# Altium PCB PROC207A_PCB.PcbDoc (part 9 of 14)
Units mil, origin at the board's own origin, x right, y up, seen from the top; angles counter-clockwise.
Board outline 4094.49 x 3724.79 mil, 8 copper layers (Top Layer, L2_GND1, L3_SIG1, L4_PWR1, L5_PWR2, L6_SIG2, L7_GND2, Bottom Layer), stack 58.1 mil thick; 584 components, 399 nets, 8440 pads, 5258 vias.
Unrouted connection lines stored in the file: 9.
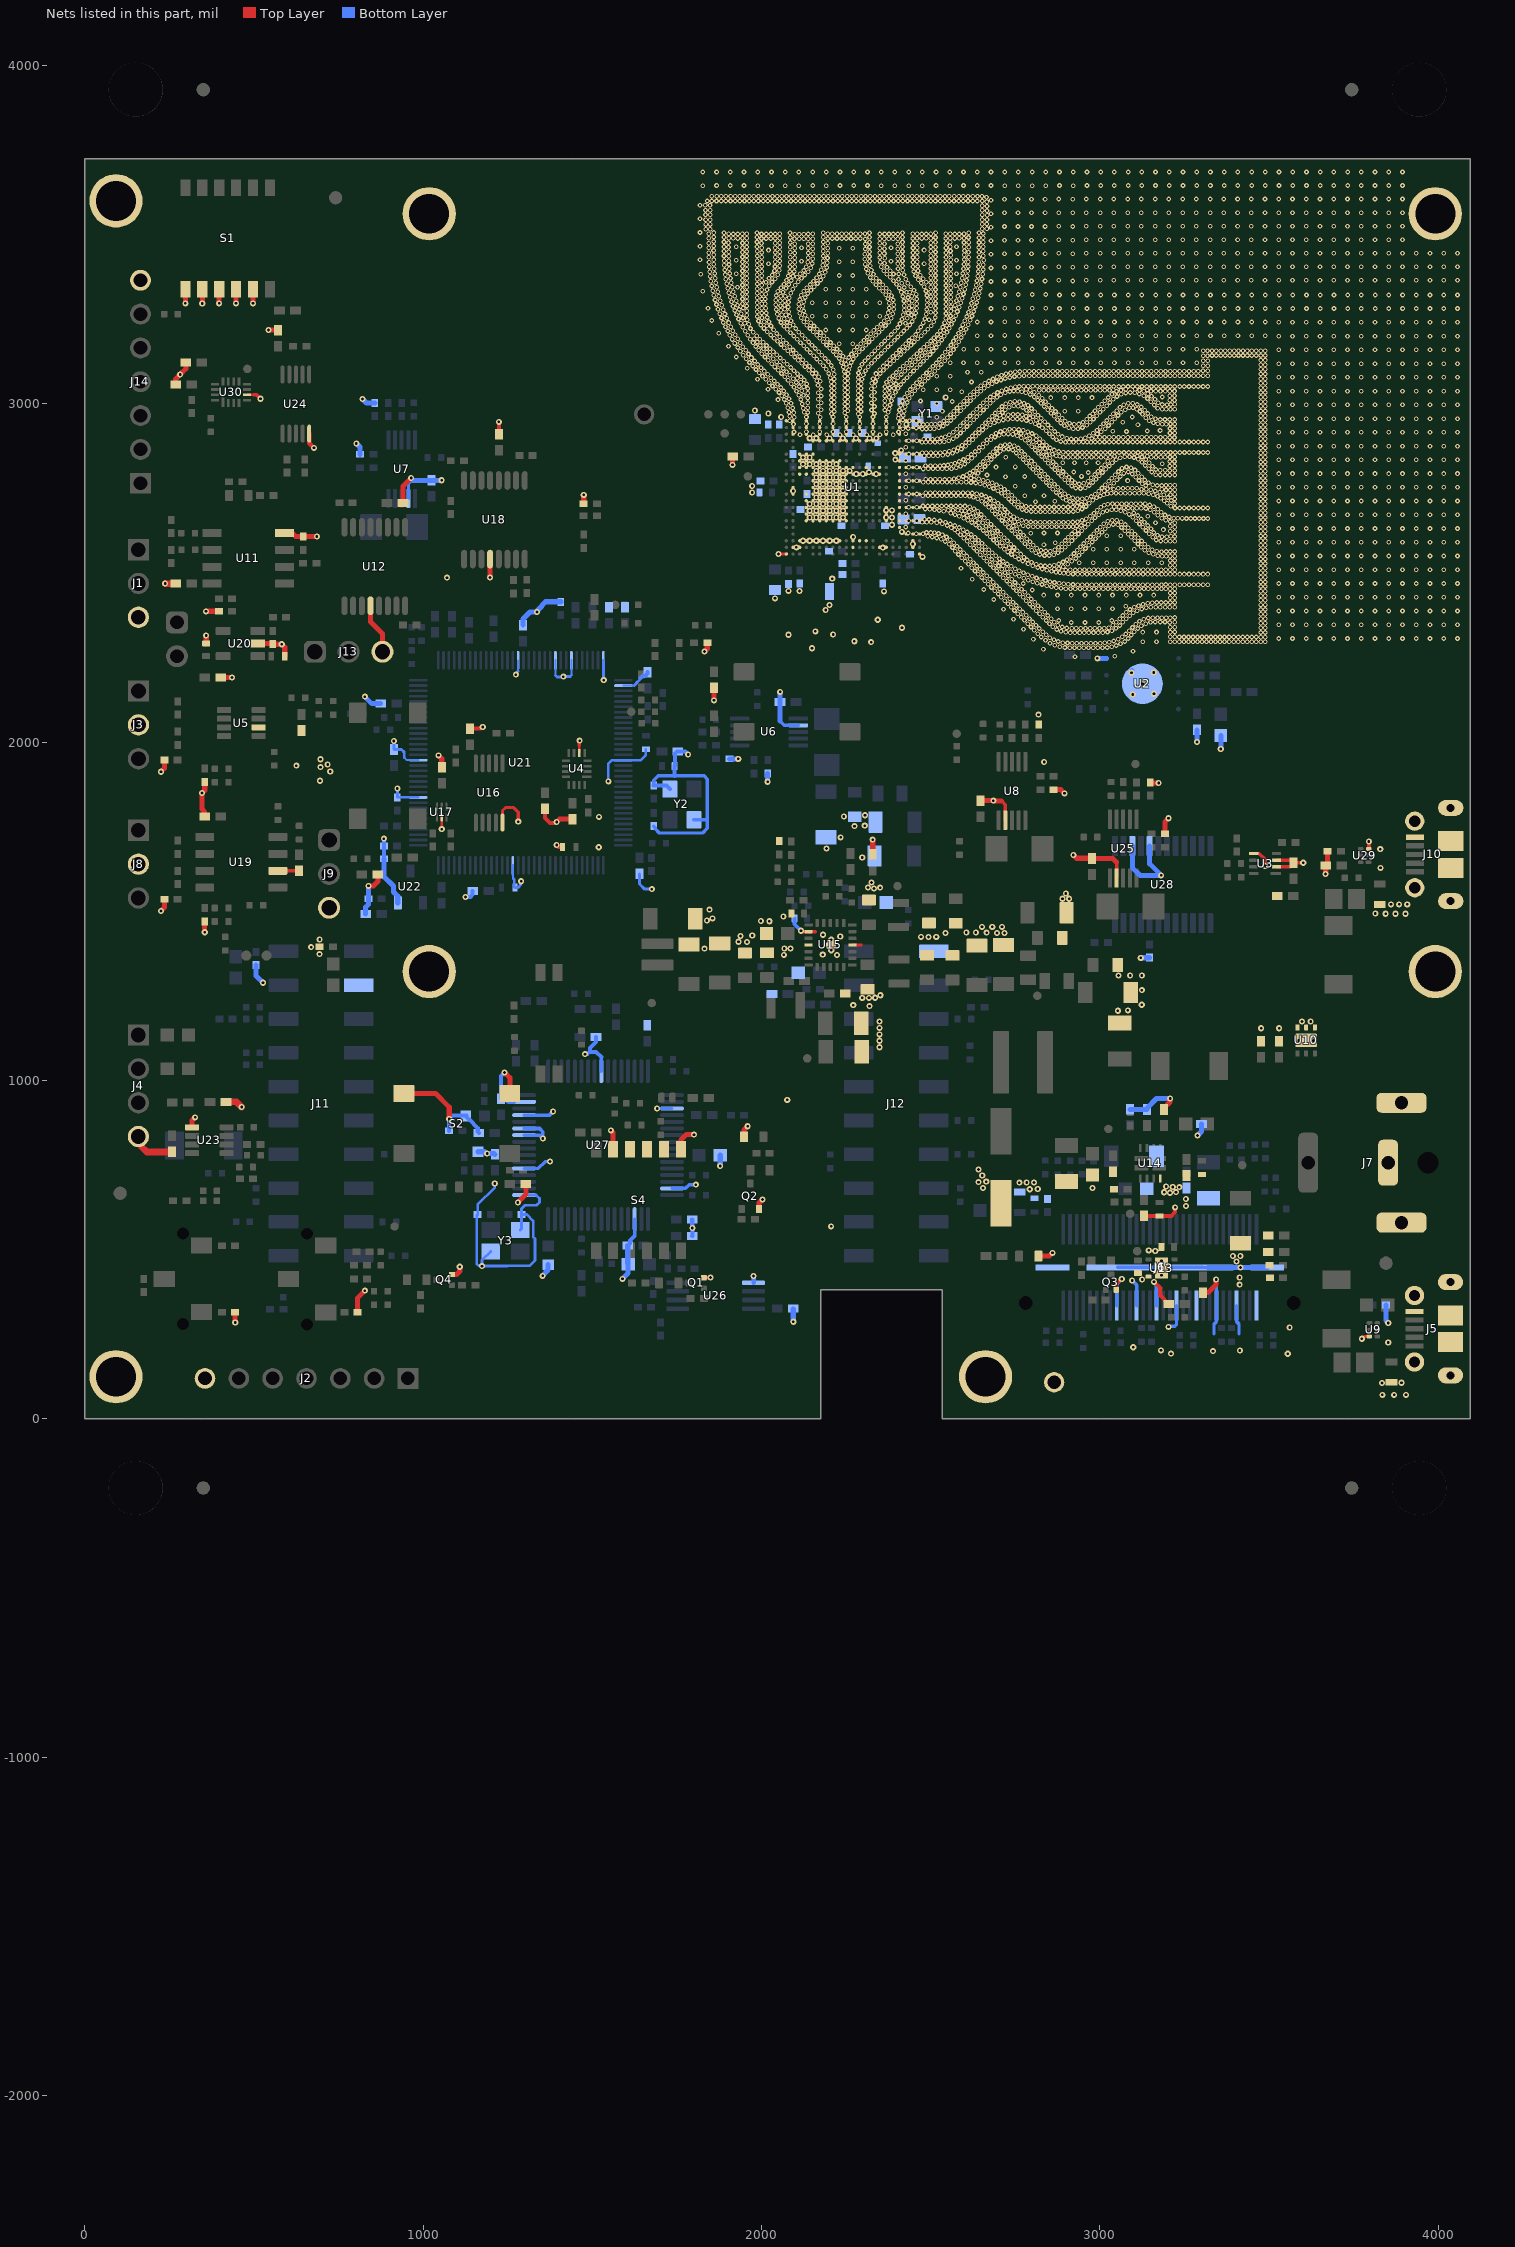
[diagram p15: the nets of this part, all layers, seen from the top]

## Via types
v1: diameter 13.77, hole 7, Top Layer to L2_GND1, tented top, 4306 vias
v2: diameter 18, hole 8, Top Layer to Bottom Layer, tented both sides, 946 vias
v3: diameter 19.68, hole 8, Top Layer to Bottom Layer, tented both sides, 6 vias

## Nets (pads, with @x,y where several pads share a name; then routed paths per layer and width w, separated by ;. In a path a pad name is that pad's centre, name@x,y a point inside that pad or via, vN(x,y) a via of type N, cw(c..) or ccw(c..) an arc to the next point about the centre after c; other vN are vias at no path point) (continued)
GND: (continued)
  other v1: 2926.59,2253.1 3044.2,2254.51 3098.09,2268.57 2833.35,2275.23 2911.35,2279.17 2925.22,2279.07 2938.99,2279.07 2952.76,2279.07 2966.53,2279.07 2980.3,2279.07 2994.39,2279.08 2896.92,2279.99 3008.14,2279.7 3021.9,2280.32 3035.58,2281.89 2881.78,2282.57 3048.76,2285.88 2866.94,2286.95 3061.39,2291.36 2852.8,2293.13 2918.34,2293.11 2932.11,2293.11 2945.88,2293.11 2959.65,2293.11 2973.42,2293.11 2987.19,2293.11 3000.96,2293.11 2904.57,2293.32 3014.71,2293.73 2890.86,2294.67 3028.39,2295.3 3126.81,2297.3 3167.44,2297.3 3208.06,2297.3 3221.57,2297.3 3235.41,2297.3 3248.75,2297.3 3262.09,2297.3 3275.43,2297.3 3288.77,2297.3 3302.1,2297.3 3315.44,2297.3 3328.78,2297.3 3342.12,2297.3 3355.46,2297.3 3368.8,2297.3 3382.14,2297.3 3395.47,2297.3 3408.81,2297.3 3422.15,2297.3 3435.49,2297.3 3448.83,2297.3 3462.17,2297.3 3475.51,2297.3 3488.84,2297.3 2877.51,2298.05 3073.43,2298.05 3041.57,2299.29 2839.39,2301.43 2864.55,2302.69 2803.81,2304.74 3054.2,2304.77 3084.07,2306.79 3529.15,2306.79 3569.78,2306.79 3610.4,2306.79 3651.03,2306.79 3691.65,2306.79 3732.28,2306.79 3772.9,2306.79 3813.53,2306.79 3854.15,2306.79 3894.78,2306.79 3935.4,2306.79 3976.03,2306.79 4016.65,2306.79 4057.28,2306.79 2852.41,2309.18 2827.35,2310.99 3235.41,2311.07 3248.75,2311.07 3262.09,2311.07 3275.43,2311.07 3288.77,2311.07 3302.1,2311.07 3315.44,2311.07 3328.78,2311.07 3342.12,2311.07 3355.46,2311.07 3368.8,2311.07 3382.14,2311.07 3395.47,2311.07 3408.81,2311.07 3422.15,2311.07 3435.49,2311.07 3448.83,2311.07 3462.17,2311.07 3475.51,2310.88 3488.84,2310.88 3066.24,2311.46 3208.06,2311.52 3221.57,2311.59 3092.61,2317.19 2841.33,2317.36 3076.88,2320.2 2816.52,2321.09 2912.67,2324.26 2926.44,2324.26 2940.21,2324.26 2953.98,2324.26 2967.75,2324.26 2981.52,2324.26 2995.29,2324.26 3009.06,2324.28 2898.92,2324.98 3475.51,2324.47 3488.84,2324.47 3022.73,2325.93 3126.81,2325.74 3167.44,2325.74 3208.06,2325.74 3221.57,2325.88 2830.99,2326.45 3102.3,2326.99 2885.48,2327.98 3035.86,2330.06 3086.9,2329.65 2806.46,2331.13 2774.27,2334.26 2872.81,2333.37 2821.25,2336.19 3112.11,2336.23 2916.61,2337.2 2930.38,2337.2 2944.15,2337.2 2957.92,2337.2 2971.69,2337.2 2985.46,2337.2 2999.23,2337.2 3013,2337.22 3048.01,2336.56 2902.73,2337.86 3475.51,2338.06 3488.84,2338.06 3026.67,2338.87 3096.63,2339.39 3208.06,2339.96 3221.57,2340.17 2796.72,2340.87 2861.33,2340.98 2889.19,2340.86 3058.66,2345.29 3123.08,2344.54 2811.52,2345.93 2876.13,2346.04 3038.34,2346.18 3529.15,2347.41 3569.78,2347.41 3610.4,2347.41 3651.03,2347.41 3691.65,2347.41 3732.28,2347.41 3772.9,2347.41 3813.53,2347.41 3854.15,2347.41 3894.78,2347.41 3935.4,2347.41 3976.03,2347.41 4016.65,2347.41 4057.28,2347.41 3106.47,2349.02 2851.19,2350.3 2786.98,2350.6 3135.4,2350.7 3475.51,2351.65 3488.84,2351.65 2915.77,2353.86 2956.4,2353.86 2997.02,2353.86 3207.21,2354.18 2865.03,2354.36 3048.99,2354.82 3068.31,2355.11 3149.76,2354.49 3221.57,2354.46 2801.78,2355.66 3164.12,2355.6 3178.49,2355.6 3192.85,2355.6 3117.44,2357.34 2841.45,2360.03 2878.75,2360.11 3035.64,2359.93 2777.25,2360.34 2744.74,2363.78 3129.76,2363.5 2856.25,2365.09 3058.6,2364.82 3078.05,2364.84 3475.51,2365.24 3488.84,2365.24 2792.04,2365.4 3143,2367.29 3156.72,2368.4 3170.49,2368.4 3183.23,2368.4 3195.96,2368.4 3208.06,2368.4 3221.57,2368.76 2767.51,2370.08 2831.72,2369.77 3088.24,2374.1 2782.3,2375.14 2846.51,2374.83 3068.27,2374.63 3475.51,2378.83 3488.84,2378.83 2757.77,2379.81 2821.98,2379.51 3099.06,2382.62 3078.52,2384.04 2772.57,2384.87 2836.78,2384.57 3529.15,2388.04 3569.78,2388.04 3610.4,2388.04 3651.03,2388.04 3691.65,2388.04 3732.28,2388.04 3772.9,2388.04 3813.53,2388.04 3854.15,2388.04 3894.78,2388.04 3935.4,2388.04 3976.03,2388.04 4016.65,2388.04 4057.28,2388.04 2812.24,2389.24 3111.21,2389.11 2748.03,2389.55 2715.53,2392.99 3089.3,2392.41 3475.51,2392.41 3488.84,2392.41 2827.04,2394.3 3124.03,2394.11 2762.83,2394.61 2875.15,2394.49 2915.77,2394.49 2956.4,2394.49 2997.02,2394.49 3037.65,2394.49 3137.29,2397.83 2738.3,2399.29 2802.51,2398.98 3101.45,2398.99 3151,2399.18 3165.07,2399.55 3179.14,2399.55 3193.2,2399.55 3207.27,2399.55 3221.34,2399.55 3076.93,2401.8 2817.3,2404.04 3114.42,2403.73 2753.09,2404.35 3475.51,2406 3488.84,2406 3127.69,2407.85 2728.56,2409.02 2792.77,2408.72 3141.58,2410.98 3155.34,2412.2 3168.53,2413.17 2743.36,2414.08 2807.57,2413.78 3181.72,2413.35 3194.92,2413.35 3208.11,2413.35 3221.3,2413.35 2718.82,2418.76 2783.03,2418.45 3475.51,2419.59 3488.84,2419.59 2686.31,2422.2 2733.62,2423.82 2797.83,2423.51 3208.44,2427.18 3221.32,2427.22 2773.3,2428.19 2709.09,2428.5 3529.15,2428.66 3569.78,2428.66 3610.4,2428.66 3651.03,2428.66 3691.65,2428.66 3732.28,2428.66 3772.9,2428.66 3813.53,2428.66 3854.15,2428.66 3894.78,2428.66 3935.4,2428.66 3976.03,2428.66 4016.65,2428.66 4057.28,2428.66 2788.09,2433.25 3475.51,2433.18 3488.84,2433.18 2723.88,2433.56 2834.52,2435.11 2875.15,2435.11 2915.77,2435.11 2956.4,2435.11 2997.02,2435.11 3037.65,2435.11 3078.27,2435.11 3118.9,2435.11 3159.52,2435.11 2699.35,2438.24 2763.56,2437.93 3208.45,2441.06 3221.33,2441.1 2714.15,2443.29 2778.36,2442.99 3475.51,2446.77 3488.84,2446.77 2689.61,2447.97 2753.82,2447.66 2800.03,2450.05 2656.9,2451.41 2704.41,2453.03 2768.62,2452.72 2899.5,2453.67 2913.45,2453.5 2927.55,2453.5 2941.58,2453.5 2955.35,2453.5 2969.12,2453.5 2982.89,2453.5 2996.66,2453.5 3010.43,2453.5 3024.2,2453.5 3037.97,2453.5 3051.74,2453.5 3065.51,2453.97 3078.5,2453.97 3091.49,2453.97 3104.49,2453.97 3117.48,2453.97 3130.47,2453.97 3143.47,2453.97 3156.46,2453.97 3169.45,2453.97 3182.45,2453.97 3195.44,2453.97 3208.43,2453.97 3221.43,2453.97 2885.13,2455.2 2870.95,2457.28 2679.88,2457.71 2744.09,2457.4 2857.09,2459.64 3475.51,2460.36 3488.84,2460.36 2694.67,2462.77 2758.88,2462.46 2842.97,2462.74 2829.23,2466.17 2934.69,2466.04 2948.46,2466.04 2962.23,2466.04 2976,2466.04 2989.77,2466.04 3003.54,2466.04 3017.31,2466.04 3031.08,2466.04 3044.85,2466.04 3058.62,2466.04 3072.39,2466.04 3086.16,2466.04 3099.93,2466.04 3113.7,2466.04 3127.47,2466.04 3141.24,2466.04 3155.01,2466.04 3168.78,2466.04 3182.55,2466.04 3208.18,2466.04 3222.06,2466.04 3235.94,2466.04 3249.82,2466.04 3263.71,2466.04 3277.57,2466.04 3291.44,2466.04 3305.3,2466.04 3319.16,2466.04 2734.35,2467.14 2907.18,2467.22 2920.93,2466.55 3194.87,2466.42 2670.14,2467.45 2893.44,2468.14 2773.99,2469.14 3529.15,2469.29 3569.78,2469.29 3610.4,2469.29 3651.03,2469.29 3691.65,2469.29 3732.28,2469.29 3772.9,2469.29 3813.53,2469.29 3854.15,2469.29 3894.78,2469.29 3935.4,2469.29 3976.03,2469.29 4016.65,2469.29 4057.28,2469.29 2815.55,2470.09 2879.82,2470.16 2749.15,2472.2 2866.2,2472.18 2684.94,2472.51 3475.51,2473.94 3488.84,2473.94 2801.85,2474.72 2852.67,2474.77 2660.4,2477.18 2724.61,2476.87 2839.32,2478.12 2788.68,2479.43 2623.14,2481.91 2675.2,2482.24 2739.41,2481.93 2825.96,2481.47 2775.36,2484.89 2812.85,2485.69 2650.67,2486.92 2714.88,2486.61 3475.51,2487.53 3488.84,2487.53 2762.25,2491 2799.89,2490.33 2665.46,2491.98 2729.67,2491.67 2786.92,2494.97 2640.93,2496.66 2705.14,2496.35 2749.7,2497.07 2934.74,2497.18 2948.51,2497.18 2962.28,2497.18 2976.05,2497.18 2989.82,2497.18 3003.59,2497.18 3017.36,2497.18 3031.13,2497.18 3044.9,2497.18 3058.67,2497.18 3072.44,2497.18 3086.21,2497.18 3099.98,2497.18 3113.75,2497.18 3127.52,2497.18 3141.29,2497.18 3155.06,2497.18 3168.83,2497.18 3182.6,2497.18 3195.05,2496.76 3208.18,2497.19 3222.06,2497.19 3235.94,2497.19 3249.82,2497.19 3263.71,2497.19 3277.57,2497.19 3291.44,2497.19 3305.3,2497.19 3319.16,2497.19 2907.22,2498.21 2920.98,2497.54 2893.51,2499.42 2774.43,2500.77 2882.23,2500.62 3475.51,2501.12 3488.84,2501.12 2655.73,2501.72 2719.93,2501.41 2870.63,2502.5 2737.02,2503.98 2857.15,2505.18 2695.4,2506.09 2631.19,2506.39 2761.99,2506.66 2843.62,2508.42 2899.1,2509.15 2926.94,2509.24 2940.87,2510.03 2954.79,2510.03 2968.71,2510.03 2982.63,2509.68 2995.9,2509.68 3009.17,2509.68 3022.44,2509.68 3035.71,2509.68 3048.98,2509.68 3062.25,2509.68 3075.52,2509.68 3088.79,2509.68 3102.06,2509.68 3115.32,2509.68 3128.59,2509.68 3141.86,2509.68 3155.13,2509.68 3168.4,2509.68 3181.67,2509.68 3194.94,2509.68 3208.21,2509.68 3221.48,2509.68 3529.15,2509.91 3569.78,2509.91 3610.4,2509.91 3651.03,2509.91 3691.65,2509.91 3732.28,2509.91 3772.9,2509.91 3813.53,2509.91 3854.15,2509.91 3894.78,2509.91 3935.4,2509.91 3976.03,2509.91 4016.65,2509.91 4057.28,2509.91 2710.2,2511.14 2913.02,2510.34 2645.99,2511.45 2830.32,2512.16 2865.55,2512.13 2726.35,2512.78 2749.64,2512.76 2879.18,2513.68 2589.56,2514.34 3475.51,2514.71 3488.84,2514.71 2621.46,2516.13 2685.66,2515.82 2816.46,2516.66 2892.24,2518.9 2737.83,2519.84 2636.25,2521.19 2700.46,2520.88 2838.25,2520.98 2852.02,2521.25 2714.21,2522.14 2801.95,2522.09 2825.7,2522.57 2865.67,2523 3208.61,2523.51 3221.49,2523.56 2611.72,2525.87 2675.93,2525.56 2811.67,2526.24 2905.32,2525.89 2726.02,2526.92 2878.85,2526.99 2787.97,2528.16 3475.51,2528.3 3488.84,2528.3 2626.51,2530.93 2690.72,2530.62 2939.68,2530.81 2980.31,2530.81 3020.93,2530.81 3061.56,2530.81 3102.18,2530.81 3142.81,2530.81 3183.43,2530.81 2703.48,2531.45 2797.94,2531.93 2891.36,2532.75 2666.19,2535.3 2714.52,2534.48 2601.98,2535.6 2772.15,2535.99 2917.27,2535.49 3208.63,2537.39 3221.5,2537.44 2785.99,2538.83 2903.18,2539.82 2616.78,2540.66 2680.99,2540.35 2760.79,2541.78 3475.51,2541.89 3488.84,2541.89 2703.46,2542.69 2928.62,2543.4 2656.45,2545.03 2592.24,2545.34 2775.86,2546.83 2749.65,2548.39 2913.82,2548.55 2671.25,2550.09 3184.99,2550.12 3196.46,2550.12 3207.99,2550.24 3221.49,2550.18 2607.04,2550.4 2692.4,2550.89 3529.15,2550.54 3569.78,2550.54 3610.4,2550.54 3651.03,2550.54 3691.65,2550.54 3732.28,2550.54 3772.9,2550.54 3813.53,2550.54 3854.15,2550.54 3894.78,2550.54 3935.4,2550.54 3976.03,2550.54 4016.65,2550.54 4057.28,2550.54 2836.41,2552.27 2850.18,2552.17 3171.36,2551.33 2938.45,2553.14 2582.51,2555.08 2646.72,2554.77 2739.18,2554.92 2822.92,2555.03 2863.7,2554.74 3157.98,2555.46 3475.51,2555.47 3488.84,2555.47 2765.88,2556.32 2923.65,2558.2 2597.3,2560.14 2661.51,2559.83 2681.9,2559.81 2876.48,2559.89 2810.22,2560.36 3144.91,2560.52 2727.84,2562.66 2948.18,2562.88 3182.3,2563.68 3196.14,2564.01 3208.62,2564.01 3221.5,2564.06 2572.77,2564.81 2636.98,2564.51 2853.55,2564.92 3168.6,2565.06 2741.86,2565.34 2756.14,2566.05 2839.9,2565.35 2798.79,2568.05 2826.29,2567.78 2888.01,2567.41 2933.39,2567.93 3133.09,2567.35 2671.7,2569.05 3475.51,2569.06 3488.84,2569.06 2587.57,2569.87 2651.78,2569.57 2866.41,2569.41 3155.5,2569.31 2717.11,2571.1 2980.31,2570.81 3020.93,2570.81 3061.56,2570.81 3102.18,2570.81 2813.59,2573.11 2957.92,2572.61 2627.24,2574.24 2732.85,2574.55 2564.43,2575.74 2746.41,2575.79 3143.63,2576.28 2878.03,2576.93 2898.14,2576.74 3122.72,2576.49 2661.5,2578.3 2788.76,2577.48 2943.12,2577.67 2642.04,2579.3 2577.83,2579.61 2706.23,2579.54 2721.87,2580.47 2803.56,2582.54 2967.66,2582.35 3475.51,2582.65 3488.84,2582.65 2617.51,2583.98 2834.84,2584.06 2554.63,2585.24 2736.67,2585.53 3112.99,2586.23 3133.23,2585.31 2779.03,2587.22 2887.77,2586.67 2907.88,2586.47 2651.76,2588.04 2952.86,2587.41 2632.3,2589.04 2696.02,2588.79 2568.09,2589.35 2712.14,2590.21 2868.76,2589.67 3529.15,2591.16 3569.78,2591.16 3610.4,2591.16 3651.03,2591.16 3691.65,2591.16 3732.28,2591.16 3772.9,2591.16 3813.53,2591.16 3854.15,2591.16 3894.78,2591.16 3935.4,2591.16 3976.03,2591.16 4016.65,2591.16 4057.28,2591.16 2793.82,2592.28 2977.39,2592.09 2543.61,2593.6 2607.77,2593.72 2726.93,2595.26 3123.49,2595.04 3180.56,2594.82 3194.5,2594.46 3208.36,2594.51 3221.5,2594.66 2917.62,2596.21 3103.25,2595.96 3475.51,2596.24 3488.84,2596.24 2641.5,2597.22 2769.29,2596.95 2897.51,2596.4 2962.6,2597.15 2685.82,2598.03 3167.16,2597.98 2558.07,2598.79 2622.57,2598.78 2531.29,2600.29 2702.4,2599.94 2784.08,2602.01 2987.13,2601.82 2517.98,2603.98 2598.03,2603.45 2717.19,2605 3113.75,2604.78 2611.07,2606.27 2630.9,2606.02 2907.24,2606.14 2927.35,2605.95 3093.51,2605.7 2504.88,2606.82 2546.99,2606.96 2759.55,2606.69 2972.34,2606.88 3156.22,2606.36 2676.11,2607.8 3183.92,2607.85 3197.47,2607.65 3221.39,2608.25 3209.35,2608.56 2491.38,2609.54 2692.66,2609.68 3475.51,2609.83 3488.84,2609.83 3020.93,2610.81 3061.56,2610.81 2774.35,2611.75 2996.87,2611.56 3170.64,2611.52 2588.3,2613.19 2534.8,2613.37 2619.67,2613.98 2599.28,2614.99 2707.46,2614.74 3104.02,2614.52 2917.38,2615.46 2937.09,2615.68 3083.78,2615.44 3146.49,2616.09 2457.68,2616.75 2477.37,2616.75 2523.19,2617.11 2665.84,2616.97 2749.81,2616.43 2982.07,2616.62 2795.57,2618.2 2434.18,2618.45 2835.01,2618.45 2875.01,2618.45 2487.76,2619.98 2500.28,2619.88 2511.21,2619.33 2682.93,2619.42 3159.79,2619.92 2579.89,2620.84 3006.61,2621.3 2608.23,2621.64 2764.61,2621.49 3221.41,2621.83 2925.56,2623.25 3094.28,2624.25 3208.53,2623.91 3475.51,2623.42 3488.84,2623.42 2697.72,2624.48 3074.16,2625.07 2655.58,2626.15 2740.08,2626.16 2946.83,2625.42 3136.75,2625.83 2991.81,2626.36 2570.93,2627.89 2596.18,2628.3 2673.19,2629.15 2935.91,2628.43 3188.1,2628.72 2754.87,2631.22 3016.34,2631.03 3151.55,2630.89 3529.15,2631.79 3569.78,2631.79 3610.4,2631.79 3651.03,2631.79 3691.65,2631.79 3732.28,2631.79 3772.9,2631.79 3813.53,2631.79 3854.15,2631.79 3894.78,2631.79 3935.4,2631.79 3976.03,2631.79 4016.65,2631.79 4057.28,2631.79 2561.4,2634.26 2687.98,2634.21 3084.54,2633.99 2584.1,2634.93 2644.5,2634.32 2956.56,2635.16 3064.13,2634.89 2426.46,2636.22 2730.34,2635.9 3001.55,2636.09 3127.01,2635.57 3221.42,2635.41 2803.06,2636.83 2816.98,2636.68 2830.75,2636.68 2844.52,2636.68 2858.29,2636.68 2872.06,2636.68 2885.83,2636.68 2908.92,2636.92 2920.86,2637.21 3475.51,2637 3488.84,2637 2788.63,2637.69 2897.59,2637.37 2663.45,2638.89 3208.09,2638.61 2743.91,2639.42 2931.48,2639.32 2548.71,2640.66 2571.46,2640.62 2773.49,2640.35 2945.05,2640.79 3026.34,2640.5 3141.81,2640.63 2633.27,2642.29 2678.25,2643.95 3039.71,2643.82 3053.47,2643.53 3074.75,2643.67 2760.67,2644.84 2966.3,2644.89 3117.28,2645.3 2534.13,2645.79 2558.38,2645.32 2720.6,2645.64 3011.55,2645.56 2955.26,2647.23 2517.87,2649.24 2642.16,2648.66 2653.71,2648.63 2733.95,2648.99 3164.67,2649.11 3221.43,2648.99 2543.84,2650.04 2621.61,2649.62 2474.84,2650.36 2488.6,2650.32 2502.16,2650.71 2796.33,2651.02 2810.1,2650.72 2823.87,2650.72 2837.64,2650.72 2851.41,2650.72 2865.18,2650.72 2878.95,2650.72 2892.72,2650.72 2906.49,2650.72 2920.25,2650.93 3132.07,2650.36 3475.51,2650.7 3488.84,2650.7 2748.82,2651.33 2933.96,2652.28 3063.39,2651.46 2782.62,2652.37 3023.22,2652.86 3208.4,2652.66 2527.43,2654.03 2668.51,2653.69 2435.21,2655.07 2459.01,2655.09 2976.18,2654.36 3107.54,2655.04 2710.87,2655.37 2769.31,2655.87 2947.25,2655.88 3036.59,2656.18 3050.35,2655.89 2510.64,2656.95 2609.47,2656.38 2631.64,2656.65 3195.05,2656.52 2495.13,2658.64 2481.7,2659.36 2645.43,2659.75 2723.75,2659.33 2737.4,2659.38 3122.33,2660.1 2756.36,2660.55 2960.03,2661 3230.91,2661.74 3243.52,2661.69 3256.12,2661.31 3268.73,2661.31 3281.34,2661.31 3293.95,2661.31 3306.55,2661.31 3319.16,2661.31 2597.52,2662.41 3182.67,2662.66 3218.3,2662.53 2658.77,2663.42 2985.86,2663.99 2620.31,2664.92 2701.13,2665.11 3097.8,2664.78 3475.51,2664.38 3488.84,2664.38 3205.11,2665.97 2745.7,2666.38 2584.67,2667.95 2971.88,2667.85 3141.55,2667.97 2608.53,2670.29 2635.64,2669.44 3112.09,2670.3 2716.94,2671.24 3171.77,2670.96 3192.92,2671.93 2571.97,2672.9 2649.04,2673.16 2735.64,2672.95 2996.45,2673.01 3529.15,2672.41 3569.78,2672.41 3610.4,2672.41 3651.03,2672.41 3691.65,2672.41 3732.28,2672.41 3772.9,2672.41 3813.53,2672.41 3854.15,2672.41 3894.78,2672.41 3935.4,2672.41 3976.03,2672.41 4016.65,2672.41 4057.28,2672.41 2596.05,2673.79 3087.16,2673.52 2691.39,2674.85 2426.46,2675.59 2558.96,2677.22 2982.77,2676.49 2624.54,2677.39 2705.05,2678.24 3100.42,2677.79 3475.51,2678.07 3488.84,2678.07 2727.24,2680.14 3008.33,2680 3075.16,2680.26 3161.23,2679.87 3181.98,2680.35 2614.09,2681.93 2797.13,2682.04 2810.9,2681.86 2824.67,2681.86 2838.44,2681.86 2852.21,2681.86 2865.98,2681.86 2879.75,2681.86 2893.52,2681.86 2907.29,2681.86 2921.06,2682.12 2538.47,2682.63 2639.2,2682.8 2783.49,2683.92 2525.16,2685.27 2591.08,2684.72 2602.44,2684.32 2681.66,2684.59 2934.64,2684.4 3021.27,2684.69 3062.18,2684.86 2551.86,2685.48 2565.94,2685.67 2579.73,2685.67 2992.6,2686.01 3034.83,2687.11 3048.6,2687.16 3149.62,2687.09 2511.56,2687.34 2719.6,2687.94 2770.39,2688.15 2497.79,2688.86 3171.71,2689.04 2483.87,2689.61 2697.76,2689.95 2947.47,2689.39 2627.97,2690.76 3136.38,2691.12 3096.58,2692.1 3109.21,2691.89 3122.72,2691.43 3475.51,2691.76 3488.84,2691.76 3071.48,2693.18 3083.86,2692.6 3222.16,2692.58 3235.94,2692.46 3249.82,2692.46 3263.71,2692.46 3277.57,2692.46 3291.44,2692.46 3305.3,2692.46 3319.16,2692.46 2435.21,2694.44 2459.01,2694.46 2671.92,2694.32 2758.24,2694.64 3003.19,2694.62 2615.23,2695.99 2795.72,2695.51 2809.49,2695.51 2823.26,2695.51 2837.03,2695.51 2850.8,2695.51 2864.57,2695.51 2878.34,2695.51 2892.11,2695.51 2905.88,2695.51 2919.65,2695.51 3042.23,2695.72 3057.9,2695.86 2685.69,2697.02 2709.4,2697.2 2959.04,2696.86 3160.01,2696.3 2491.48,2698.3 2505.25,2698.3 2519.02,2698.3 2532.79,2698.3 2546.56,2698.3 2560.33,2698.3 2574.1,2698.3 2587.87,2698.3 2601.64,2698.21 2781.94,2697.88 2932.81,2698.04 3209.41,2697.59 2477.5,2698.61 3013.1,2700.15 2769.3,2701.97 3147.27,2701.53 2945.97,2702.94 2662.14,2704.02 2747.58,2703.35 3023.84,2703.35 3133.84,2704.57 2699.02,2706.24 2969.17,2706.19 3037.47,2705.32 3051.24,2705.39 3065.01,2705.39 3078.78,2705.39 3092.55,2705.39 3106.32,2705.39 3120.09,2705.39 3221.5,2705.93 3475.51,2705.45 3488.84,2705.45 2676.04,2706.81 3199.83,2706.34 2922.85,2708.8 2936.5,2708.88 2759.04,2710.91 2956.89,2710.89 2739.17,2711.32 2810.12,2711.47 2911.53,2711.77 2651.5,2712.75 2866.9,2712.92 3529.15,2713.04 3569.78,2713.04 3610.4,2713.04 3651.03,2713.04 3691.65,2713.04 3732.28,2713.04 3772.9,2713.04 3813.53,2713.04 3854.15,2713.04 3894.78,2713.04 3935.4,2713.04 3976.03,2713.04 4016.65,2713.04 4057.28,2713.04 2687.57,2713.89 3190.58,2714.16 2426.46,2714.96 2664.84,2714.92 2979.61,2715.14 3210.72,2714.52 2900.53,2715.63 3221.42,2719.27 3475.51,2719.14 3488.84,2719.14 2639.58,2719.65 2731.14,2719.31 2748.76,2720.07 2934.02,2719.72 2947.79,2719.49 2675.58,2720.67 2890.82,2721.65 2961.38,2721.72 3180.5,2721.33 2920.51,2722.38 2990.3,2722.49 3200.47,2723.54 2626.82,2724.7 2663.15,2726.59 2974.36,2726.32 3170.52,2726.78 2614.84,2727.71 2907.68,2727.39 3000.85,2728.05 2476.82,2729.07 2492.23,2729.1 2505.98,2729.09 2519.79,2728.97 2533.64,2728.97 2547.37,2729.04 2561.15,2729.13 2575.05,2728.98 2588.85,2729.03 2602.7,2729.03 2720.79,2728.39 2777.97,2728.64 2834.98,2729.08 2882.22,2730 2650.11,2731.02 2739.96,2730.32 3011.34,2732.07 3157.66,2731.83 3189.51,2731.88 3209.12,2732 2986.32,2733.14 3221.67,2732.62 3475.51,2732.83 3488.84,2732.83 2435.21,2733.81 2459.01,2733.83 2636.75,2734.33 2895.95,2734.6 3022.57,2734.75 3144.17,2734.79 3033.98,2736.08 3130.35,2736.01 2623.18,2736.7 2709.59,2736.4 3047.74,2736.54 3061.51,2736.54 3075.28,2736.54 3089.05,2736.54 3102.82,2736.54 3116.59,2736.54 2485.51,2737.67 2499.28,2737.67 2513.05,2737.67 2526.82,2737.67 2540.59,2737.67 2554.36,2737.67 2568.13,2737.67 2581.9,2737.67 2595.67,2737.67 2609.44,2737.6 2871.11,2738.21 3177.49,2738.62 2729.6,2739.4 2996.88,2741.98 3013.69,2743.02 3164.33,2742.81 2698.07,2743.94 2885.54,2743.61 3195.81,2745.55 3208.65,2745.55 3221.5,2745.97 3151.01,2746.5 3475.51,2746.52 3488.84,2746.52 2718.41,2747.42 2861.01,2748.29 3040.71,2747.82 3123.15,2748.18 3137.14,2748.3 3182.88,2748.05 2685.78,2750.16 2942.96,2749.98 3022.87,2749.32 3054.4,2750.57 3068.4,2750.58 3082.17,2750.58 3095.94,2750.58 3109.71,2750.58 2929.31,2751.75 3006.61,2751.71 2956.51,2752.48 2875.8,2753.35 3529.15,2753.66 3569.78,2753.66 3610.4,2753.66 3651.03,2753.66 3691.65,2753.66 3732.28,2753.66 3772.9,2753.66 3813.53,2753.66 3854.15,2753.66 3894.78,2753.66 3935.4,2753.66 3976.03,2753.66 4016.65,2753.66 4057.28,2753.66 2426.46,2754.33 2706.89,2754.96 2673.25,2755.86 2749.68,2756.92 3031.15,2756.39 2806.69,2757.37 2851.27,2758.02 2916.87,2757.65 2968.72,2758.83 3135.91,2758.88 3170.12,2758.95 3182.96,2758.95 2660.21,2760.28 3195.81,2759.32 3208.65,2759.32 3221.5,2759.32 3475.51,2760.21 3488.84,2760.21 2694.6,2761.17 3156.5,2761.01 3016.35,2761.45 2866.07,2763.08 2939.72,2763.3 2646.91,2763.87 3125.7,2763.86 2953.06,2765.77 3040.88,2766.13 2633.41,2766.56 2682.06,2766.87 2906.49,2766.71 3143.94,2766.66 2619.25,2767.94 2841.54,2767.76 2926.55,2767.52 2978.93,2768.08 2478.05,2768.62 2492.4,2768.82 2506.74,2768.82 2520.51,2768.82 2534.28,2768.82 2548.44,2768.58 2562.6,2768.58 2576.76,2768.58 2590.92,2768.35 2605.09,2768.46 2669.02,2771.3 3026.09,2771.19 2965.47,2771.96 2435.21,2773.18 2459.01,2773.2 2856.33,2772.82 3082.12,2773.59 3115.84,2773.71 3475.51,2773.9 3488.84,2773.9 2655.73,2774.89 2917.71,2774.68 3050.62,2775.87 3133.3,2775.4 2541.44,2776.94 2629.17,2776.83 2896.75,2776.44 2485.1,2777.35 2499.7,2777.35 2513.51,2777.35 2527.28,2777.35 2555.28,2777.54 2831.8,2777.5 2988.67,2777.81 2569,2778.82 2642.24,2779.08 2604.89,2779.38 3035.82,2780.92 2582.54,2781.49 2618.16,2781.31 2975.21,2781.69 2846.59,2782.56 2908.89,2782.94 3106.06,2783.44 2721.4,2785.21 3123.56,2785.14 2595.55,2785.67 2778.41,2785.65 2887.02,2786.18 2946.1,2785.83 3060.36,2785.6 2822.06,2787.24 2998.4,2787.55 3475.51,2787.59 3488.84,2787.59 2628.9,2788.36 2666.37,2789.99 3179.01,2790.1 3193.1,2790.1 3207.19,2790.1 3221.29,2790.1 2606.49,2790.53 2900.78,2790.53 3045.56,2790.66 3165.26,2790.78 2836.86,2792.29 2984.95,2791.43 3096.33,2793.16 2426.46,2793.7 3529.15,2794.29 3569.78,2794.29 3610.4,2794.29 3651.03,2794.29 3691.65,2794.29 3732.28,2794.29 3772.9,2794.29 3813.53,2794.29 3854.15,2794.29 3894.78,2794.29 3935.4,2794.29 3976.03,2794.29 4016.65,2794.29 4057.28,2794.29 3070.7,2794.7 3113.83,2794.87 2615.95,2795.8 2640.07,2795.75 2877.28,2795.92 2812.32,2796.97 3008.14,2797.29 2966.22,2797.49 2923.39,2799 3083.83,2798.85 3154.01,2798.73 2891.04,2800.27 2994.68,2801.17 3055.3,2800.4 3475.51,2801.28 3488.84,2801.28 2625.43,2801.69 2827.12,2802.03 3178.9,2803.88 3193,2803.88 3207.09,2803.42 3221.18,2803.4 3104.09,2804.61 2650.69,2805.35 2867.54,2805.65 3165.35,2806.26 2802.59,2806.71 3017.88,2807.02 2478.05,2807.99 2492.4,2808.19 2506.74,2808.19 2520.51,2808.19 2534.28,2808.19 2548.05,2808.19 2561.81,2808.9 3144.28,2808.47 2881.31,2810 3065.64,2809.49 2635.9,2810.64 3004.42,2810.9 2575.33,2811.51 2817.38,2811.77 3092.43,2811.94 2435.21,2812.55 2459.01,2812.57 2693.11,2813.49 2750.12,2813.93 3078.77,2813.64 2660.66,2815.09 3475.51,2814.96 3488.84,2814.96 2588.32,2816.07 2857.81,2815.39 3155.63,2815.84 2484.9,2816.98 2499.7,2817.04 2513.51,2817.05 2527.46,2817.13 2792.85,2816.45 3027.61,2816.76 3206.99,2816.74 3221.08,2816.69 2539.24,2817.98 3134.54,2818.21 2550.13,2819.68 2645.86,2820.15 2871.57,2819.74 3014.16,2820.64 2561.3,2822.1 2807.65,2821.51 2600.51,2822.48 3184.4,2823.08 2572.1,2825.15 2670.39,2824.82 2848.07,2825.13 2783.11,2826.18 2890.36,2825.89 2925.2,2826.17 2960.05,2826.17 2994.9,2826.17 3145.98,2825.9 3037.35,2826.5 3124.78,2827.92 3475.51,2828.65 3488.84,2828.65 2584.9,2830.05 2655.6,2829.88 2861.83,2829.48 3206.88,2830.07 3220.98,2829.99 2611.62,2830.61 2797.91,2831.24 3023.89,2830.38 2426.46,2833.07 2838.33,2834.86 3048.13,2835.07 3529.15,2834.91 3569.78,2834.91 3610.4,2834.91 3651.03,2834.91 3691.65,2834.91 3732.28,2834.91 3772.9,2834.91 3813.53,2834.91 3854.15,2834.91 3894.78,2834.91 3935.4,2834.91 3976.03,2834.91 4016.65,2834.91 4057.28,2834.91 2597.2,2835.77 2678.85,2835.82 2773.38,2835.92 3113.79,2836.22 3136.27,2835.69 2852.1,2839.22 2621.68,2840.01 2665.33,2839.62 2788.17,2840.98 3060.54,2841.04 2721.84,2842.22 3101.21,2841.81 2609.16,2842.47 2892.71,2842.79 2906.26,2843.01 2920.15,2843.01 2934.03,2843.01 2947.89,2843.01 2961.78,2843.01 2975.66,2843.01 2989.54,2843.01 3003.42,2843.01 3017.29,2843.01 3031,2842.88 3124.62,2843.09 3152.43,2843.01 3166.31,2843.01 3179.95,2843.01 3193.83,2843.01 3221.35,2843.29 3475.51,2842.34 3488.84,2842.34 3073.93,2844.23 3207.47,2843.39 2828.6,2844.6 2881.86,2845.13 3043.31,2845.28 3087.7,2844.49 2688.6,2845.97 2763.64,2845.66 3140.61,2845.79 2870.83,2847.09 3110.83,2846.36 2480.76,2847.37 2493.89,2847.31 2507.71,2847.36 2521.18,2847.41 2535.58,2848.2 2630.85,2848.54 2842.36,2848.95 2675.07,2849.36 2550.33,2850.6 2620.49,2850.5 2778.44,2850.72 2435.21,2851.92 2459.01,2851.94 2860.36,2851.49 2697.62,2853.71 2564.5,2854.65 2753.53,2855.01 2818.86,2854.34 2475.17,2856.28 2487.03,2855.78 2500.8,2855.78 2514.57,2855.78 2528.34,2855.96 3475.51,2856.03 3488.84,2856.03 2892.5,2857.21 2906.38,2856.71 2920.14,2856.71 2933.9,2856.71 2947.66,2856.71 2961.42,2856.71 2975.18,2856.71 2988.94,2856.71 3002.7,2856.71 3016.46,2856.71 3030.21,2856.71 3043.97,2856.71 3057.73,2856.71 3071.49,2856.71 3085.25,2856.71 3099.01,2856.71 3112.77,2856.71 3126.53,2856.71 3140.29,2856.71 3154.05,2856.71 3167.81,2856.71 3181.57,2856.71 3195.33,2856.71 3209.09,2856.71 3222.85,2856.59 3236.61,2856.59 3250.36,2856.59 3264.12,2856.59 3277.88,2856.59 3291.64,2856.59 3305.4,2856.59 3319.16,2856.59 2541.92,2857.33 2684.81,2859.09 2832.62,2858.69 2555.31,2860.07 2577.95,2860.05 2631.42,2859.47 2706.16,2860.23 2849.39,2860.08 2878.86,2859.4 2642.55,2860.57 2768.7,2860.45 2742.84,2864.06 2809.12,2864.07 2865.86,2863.73 2568.4,2864.4 2716.64,2865.79 2590.99,2866.96 2730.11,2866.74 2838.17,2867.92 2694.79,2868.58 2822.88,2868.43 2580.99,2870.21 2758.59,2869.8 2853.69,2870.02 3475.51,2869.72 3488.84,2869.72 2643.37,2871.19 2653.98,2871.86 2426.46,2872.44 2799.39,2873.81 2603.21,2875.44 2706.39,2875.99 3529.15,2875.54 3569.78,2875.54 3610.4,2875.54 3651.03,2875.54 3691.65,2875.54 3732.28,2875.54 3772.9,2875.54 3813.53,2875.54 3854.15,2875.54 3894.78,2875.54 3935.4,2875.54 3976.03,2875.54 4016.65,2875.54 4057.28,2875.54 2746.76,2876.84 2829.48,2877.22 2592.66,2877.56 2813.15,2878.16 2842.5,2878.12 2719.6,2879.89 2733.37,2880.07 2655.01,2882.73 2665.93,2883.7 2789.65,2883.55 3475.51,2883.41 3488.84,2883.41 2614.18,2884.9 2603.45,2886.01 2821.41,2885.83 2474.49,2886.47 2485.42,2886.49 2499.19,2886.49 2512.96,2886.49 2526.73,2886.77 2898.54,2887.29 2922.3,2887.27 2540.43,2888.1 2803.14,2888.15 2832.71,2887.82 2910.18,2887.39 2937.34,2887.34 2951.16,2887.69 2962.85,2887.42 2974.12,2887.33 2986.11,2887.74 2999.99,2887.74 3013.87,2887.74 3027.75,2887.74 3041.63,2887.74 3055.51,2887.74 3069.4,2887.74 3083.26,2887.74 3097.14,2887.74 3111.02,2887.74 3124.91,2887.74 3138.79,2887.74 3152.65,2887.74 3166.53,2887.74 3180.42,2887.74 3194.3,2887.74 3208.18,2887.74 3222.06,2887.74 3235.94,2887.74 3249.82,2887.74 3263.71,2887.74 3277.57,2887.74 3291.44,2887.74 3305.3,2887.74 3319.16,2887.74 2884.99,2889.04 2435.21,2891.29 2459.01,2891.31 2553.72,2891.72 2779.41,2892.76 2872.15,2894.21 2623.95,2894.56 2666.71,2894.52 2677.63,2894.34 2812.11,2894.37 2479.85,2895.57 2492.24,2895.55 2505.56,2895.63 2613.48,2895.45 2929.61,2895.53 2519.21,2896.93 2822.56,2897.2 2915.86,2896.39 2943.31,2896.88 3475.51,2897.1 3488.84,2897.1 2566.28,2897.36 2793.41,2897.89 2976.27,2897.89 2902.37,2899.12 2531.09,2899.51 2768.09,2900.6 2956.58,2900.56 2988.12,2901.16 3207.17,2901.04 3220.95,2901.01 2999.87,2901.44 3013.75,2901.44 3027.64,2901.44 3041.52,2901.44 3055.4,2901.44 3069.28,2901.44 3083.15,2901.44 3096.93,2901.44 3110.71,2901.44 3124.49,2901.44 3138.27,2901.44 3152.05,2901.44 3165.83,2901.44 3179.61,2901.44 3193.39,2901.44 2543.03,2903.1 2690.09,2902.35 2861.16,2902.31 2889.37,2903.67 2577.81,2904.9 2623.22,2905.18 2633.81,2904.49 2679.79,2904.89 2755.96,2906.26 2782.34,2906 2811.63,2905.69 2969.22,2906.01 2702.82,2907.63 2113.92,2909.38 2153.29,2909.38 2192.66,2909.38 2232.03,2909.38 2271.4,2909.38 2310.77,2909.38 2350.14,2909.38 2389.51,2909.38 2555.28,2909.4 2742.28,2909.99 2877.23,2910.16 2716.5,2910.71 2992.98,2911.2 3475.51,2910.79 3488.84,2910.79 2426.46,2911.81 2729.65,2911.49 2851.46,2911.98 2693.26,2912.99 2767.21,2912.81 2799.74,2912.58 2981,2913.15 2588.07,2914.08 2643.36,2914.09 3221.41,2914.27 2632.56,2915.22 3207.54,2914.33 3529.15,2916.16 3569.78,2916.16 3610.4,2916.16 3651.03,2916.16 3691.65,2916.16 3732.28,2916.16 3772.9,2916.16 3813.53,2916.16 3854.15,2916.16 3894.78,2916.16 3935.4,2916.16 3976.03,2916.16 4016.65,2916.16 4057.28,2916.16 2096.15,2917.11 2405.12,2917.11 2566.88,2916.81 2752.41,2916.4 2132.78,2918.14 2172.15,2918.14 2211.52,2918.14 2250.89,2918.14 2290.26,2918.14 2329.63,2918.14 2369,2918.14 2787.06,2918.17 2706.32,2918.53 2866.43,2918.71 3004.8,2918.31 3079.08,2918.59 3037.94,2919.73 3140.46,2920.19 2841.41,2921.24 2773.86,2922.18 2991.56,2921.99 3178.19,2921.55 2653.51,2923.09 2719.5,2922.49 2597.81,2923.81 2642.42,2924.98 2733.05,2924.82 2760.13,2924.71 3475.51,2924.48 3488.84,2924.48 2475.41,2925.92 2487.26,2926.01 2499.11,2926.3 2577.53,2925.55 2746.68,2925.62 2417.48,2927.12 2510.96,2926.95 2921.69,2926.92 2935.46,2927.21 3016.15,2926.61 2434.18,2927.42 2856.4,2928.14 3207.54,2927.63 3221.41,2927.54 2457.68,2929.12 2524.44,2929.75 2830.43,2929.74 2908.21,2929.7 2664.72,2931.26 2948.82,2930.55 3001.35,2931.67 2607.54,2933.55 2537.23,2934.86 2587.29,2935.26 2652.43,2934.39 2820.37,2936.2 2895.67,2935.4 2961.07,2936.83 3025.88,2936.35 2846.66,2937.88 3475.51,2938.17 3488.84,2938.17 2676.21,2938.45 3112.72,2938.6 2467.08,2939.76 2478.31,2939.47 2489.51,2939.56 2501.34,2939.67 2513.17,2940.3 2923.94,2940.08 3184.54,2940.24 3196.83,2940.24 2094.45,2940.61 2406.82,2940.61 2937.52,2940.6 3209.12,2940.93 3221.41,2940.81 2132.79,2941.94 2172.16,2941.94 2211.53,2941.94 2250.9,2941.94 2290.27,2941.94 2329.64,2941.94 2369.01,2941.94 2548.93,2942.12 2808.97,2941.93 3011.09,2941.41 3171.48,2941.96 2526.74,2942.47 2617.28,2943.29 2910.57,2942.92 2662.17,2944.13 2688.52,2944.1 2884.73,2943.76 2597.02,2945 3158.63,2944.31 2950.47,2945.55 2971.48,2945.85 3035.62,2946.08 3067.72,2945.87 2796.33,2947.2 2823.82,2947.08 2836.92,2947.61 2701.31,2948.89 2898.37,2948.46 2437.64,2950.1 2457.33,2950.1 2538.43,2949.74 2083.22,2950.79 2559.23,2951.26 2783.1,2951.17 3020.82,2951.14 3146.39,2950.62 2812.39,2952.29 3475.51,2951.86 3488.84,2951.86 2417.74,2952.51 2627.02,2953.02 2682.78,2953.1 2714.73,2952.55 2671.9,2953.87 2769.75,2954.01 2875.04,2953.54 3178.41,2954.23 3192.71,2954.23 3207.02,2954.23 3221.32,2954.07 2606.76,2954.74 2728.44,2954.86 2960.99,2954.6 2742.2,2955.89 2756.03,2955.54 2981.22,2955.58 3044.19,2956.07 3164.79,2956.25 3529.15,2956.79 3569.78,2956.79 3610.4,2956.79 3651.03,2956.79 3691.65,2956.79 3732.28,2956.79 3772.9,2956.79 3813.53,2956.79 3854.15,2956.79 3894.78,2956.79 3935.4,2956.79 3976.03,2956.79 4016.65,2956.79 4057.28,2956.79 2403.83,2957.67 2792.85,2958.08 2827.18,2957.35 2888.68,2958.24 2548.74,2958.87 2173.19,2960.29 2694.99,2960 3136.08,2959.74 2096.9,2960.7 2518.22,2961.03 2568.97,2960.99 3030.56,2960.88 2132.79,2961.62 2211.53,2961.62 2250.9,2961.62 2290.27,2961.62 2329.64,2961.62 2369.01,2961.62 2802.65,2962.03 3095.7,2961.43 2636.75,2962.76 2865.3,2963.28 3152.55,2962.56 2083.27,2963.44 2681.64,2963.6 2716.33,2963.93 2781.86,2963.81 2970.68,2964.29 2616.5,2964.47 2418.5,2965.91 2990.95,2965.32 3053.93,2965.8 3475.51,2965.54 3488.84,2965.54 2703.82,2966.62 2817.45,2967.09 2469.83,2968.16 2770.94,2968.19 2878.94,2967.97 2405.21,2968.67 2558.48,2968.61 2729.52,2968.59 2743.39,2969.28 2757.27,2969.09 3126.34,2969.48 2578.71,2970.73 3040.3,2970.62 2206.75,2971.46 2285.49,2971.46 2333.94,2971.76 2792.92,2971.76 2978.89,2971.45 3142.23,2971.68 2167.44,2972.66 2646.49,2972.5 2855.56,2973.02 2246.1,2973.71 2626.23,2974.21 2691.38,2973.34 2095.28,2974.61 2126.16,2975.28 2137.13,2974.69 2712.24,2974.79 3000.69,2975.06 2081.12,2975.51 2374.23,2975.64 3063.56,2975.64 2807.71,2976.82 2215.49,2977.62 2294.23,2977.62 2869.18,2977.73 3118.67,2977.77 2421.97,2978.31 2534.81,2978.74 2568.21,2978.35 2895.89,2978.93 2936.46,2978.93 3475.51,2979.23 3488.84,2979.23 2255.22,2979.61 2985.9,2980.11 2588.44,2980.47 3050.03,2980.35 2325.06,2982.2 2364.52,2982.13 2408.07,2982.13 2656.23,2982.24 2783.18,2981.5 3132.5,2981.42 2176.26,2982.89 2701.11,2983.08 2720.61,2982.63 2845.83,2982.75 2635.97,2983.95 3074.91,2983.44 2206.66,2984.85 2285.4,2984.85 3010.43,2984.79 3109.08,2984.55 3184.37,2984.88 3196.7,2984.88 3209.02,2984.88 3221.35,2984.88 2246.41,2986 2123.84,2986.91 2377.36,2986.34 2797.97,2986.56 2858.75,2986.96 2091.97,2988.15 2577.95,2988.08 3170.78,2987.59 2077.32,2988.8 2137.05,2989.01 3086.71,2989.16 3098.28,2988.72 2598.18,2990.2 2732.06,2990.16 2772.06,2989.67 2995.63,2989.85 3059.67,2990.19 3122.72,2991.12 2215.49,2991.39 2294.23,2991.39 2424.92,2991.86 2665.96,2991.97 2255.16,2992.96 2333.88,2992.7 2711.07,2992.59 2836.09,2992.49 3475.51,2992.92 3488.84,2992.92 2167.52,2993.47 2645.71,2993.68 2758.96,2993.41 2745.23,2994.35 3020.17,2994.53 2364.52,2995.9 2411.69,2995.42 2787.69,2995.71 2379.99,2996.85 2849,2996.72 3160.84,2997.12 2206.77,2998.16 2285.51,2998.16 2587.69,2997.82 3071.02,2997.99 3198.47,2997.81 3529.15,2997.41 3569.78,2997.41 3610.4,2997.41 3651.03,2997.41 3691.65,2997.41 3732.28,2997.41 3772.9,2997.41 3813.53,2997.41 3854.15,2997.41 3894.78,2997.41 3935.4,2997.41 3976.03,2997.41 4016.65,2997.41 4057.28,2997.41 3111.15,2998.58 3185.04,2998.66 3210,2998.6 3221.43,2998.79 2120.2,3000.02 2246.41,2999.77 2607.92,2999.94 3005.37,2999.59 2722.46,3000.33 2072.83,3001.87 2087.13,3002.23 2518.22,3001.59 2675.7,3001.71 2826.35,3002.23 3084.14,3002.17 2324.91,3003 2775.78,3002.64 3097.91,3002.37 2137.06,3003.34 2176.49,3003.89 2655.44,3003.43 3029.9,3004.27 3172.91,3003.77 2215.49,3005.16 2294.23,3005.16 2430.35,3004.41 2735.27,3005.39 2255.22,3006.77 2762.61,3006.65 2839.33,3006.65 3151.11,3006.86 3475.51,3006.61 3488.84,3006.61 2416.96,3008.14 2563.49,3007.42 2597.42,3007.56 2748.87,3007.53 2469.83,3008.72 2364.52,3009.67 2384.42,3009.89 2617.65,3009.68 3015.11,3009.33 3207.07,3010.76 3220.95,3010.76 2206.65,3011.73 2285.4,3011.73 2685.44,3011.45 2816.58,3011.93 2048.63,3013.05 2115.78,3013.06 2665.79,3012.51 2067.54,3013.41 2167.37,3014.04 2246.41,3013.54 2333.92,3013.56 3039.85,3013.79 3163.17,3013.51 2081.09,3015.27 3140.91,3016.12 2436.85,3016.75 2607.16,3017.29 2829.57,3016.41 2137.03,3017.66 2215.49,3018.93 2294.23,3018.93 2855.33,3018.93 2895.89,3018.93 2936.46,3018.93 2977.02,3018.93 3025.06,3019.06 2377.04,3020.3 2627.39,3019.41 2696.01,3020.27 3475.51,3020.3 3488.84,3020.3 2255.16,3020.61 2423.3,3020.37 2676,3020.79 2806,3020.73 3184.6,3020.73 3050.79,3022.15 2389.82,3022.55 3152.98,3022.77 2176.45,3023.73 2324.95,3024.16 2364.52,3023.44 3129.55,3023.9 2059.79,3024.49 3207.07,3024.46 3220.95,3024.46 2109.97,3025.55 2124.25,3025.73 2206.88,3025.61 2285.62,3025.61 2819.14,3025.64 2073.9,3027.01 2616.9,3027.03 2246.41,3027.31 2686.65,3027.75 2707.71,3027.54 2794.22,3027.88 2443.98,3028.4 2637.45,3028.82 3036.2,3028.62 3063.03,3028.46 3117,3029.56 3141.62,3030.55 2136.89,3031.98 2430.49,3032.11 2215.49,3032.7 2294.23,3032.7 2720.26,3033.18 3076.24,3032.36 3103.65,3032.93 2051.79,3033.8 2167.31,3033.7 2377.99,3033.75 2697.59,3033.81 2781.61,3033.39 2806.69,3034.24 3089.92,3033.92 3475.51,3033.99 3488.84,3033.99 2255.06,3034.47 2333.86,3034.83 2395.91,3034.9 2592.17,3036.1 2364.52,3037.21 2626.95,3036.44 2733.5,3036.98 2769.24,3036.61 3049.43,3037.12 2065.86,3038.19 2103.62,3037.76 2647.8,3037.9 2745.41,3038.27 2757.76,3038.15 3130,3037.35 3151.55,3038.16 3165.43,3038.16 3179.31,3038.16 3193.19,3038.16 3207.07,3038.16 3220.95,3038.16 3529.15,3038.04 3569.78,3038.04 3610.4,3038.04 3651.03,3038.04 3691.65,3038.04 3732.28,3038.04 3772.9,3038.04 3813.53,3038.04 3854.15,3038.04 3894.78,3038.04 3935.4,3038.04 3976.03,3038.04 4016.65,3038.04 4057.28,3038.04 2118.86,3038.79 2206.73,3039.06 2285.47,3039.06 2452.57,3039.08 2710.15,3039.52 2246.41,3041.08 2794.53,3040.53 2820.59,3040.53 2834.47,3040.53 2848.35,3040.53 2862.23,3040.53 2876.11,3040.53 2890,3040.53 2903.88,3040.53 2917.74,3040.53 2931.62,3040.53 2945.51,3040.53 2959.39,3040.53 2973.27,3040.53 2987.14,3040.53 3001.02,3040.53 3014.9,3040.53 3028.78,3040.53 3062.73,3040.97 3117.48,3040.67 3140.24,3041.29 2478.22,3042.15 2518.22,3042.15 2558.22,3042.15 3039.52,3041.56 2019.21,3043.11 2439.27,3042.72 2042.05,3043.53 2723.12,3044.17 2782.08,3043.97 3076.44,3043.43 3104.32,3043.5 2176.22,3044.46 2324.92,3045.24 2136.78,3045.65 2637.31,3045.52 2658.91,3046.03 2215.49,3046.47 2294.23,3046.47 2378.39,3047.28 2391.7,3046.85 2403.44,3046.43 2255.14,3047.73 2736.4,3047.83 3475.51,3047.68 3488.84,3047.68 2056.92,3048.66 2095.97,3049.21 2462.07,3049.15 2124.58,3050.57 2365.08,3050.97 2749.8,3050.42 2111.21,3051.66 2761.98,3051.78 3015.01,3051.86 3028.33,3051.86 3041.65,3051.86 3055.53,3051.86 3069.4,3051.86 3083.28,3051.86 3097.16,3051.86 3111.04,3051.86 3124.92,3051.86 3138.79,3051.86 3152.67,3051.86 3166.55,3051.86 3180.43,3051.86 3194.31,3051.86 3208.18,3051.86 3222.06,3051.86 3235.94,3051.86 3249.82,3051.86 3263.71,3051.86 3277.57,3051.86 3291.44,3051.86 3305.3,3051.86 3319.16,3051.86 2032.31,3053.27 2206.75,3052.42 2285.49,3052.42 2334.32,3052.83 2448.64,3052.81 2775.3,3052.32 2788.61,3052.32 2801.93,3052.32 2815.25,3052.32 2828.57,3052.32 2841.88,3052.32 2855.2,3052.32 2868.52,3052.32 2881.84,3052.32 2895.16,3052.32 2908.47,3052.32 2921.79,3052.32 2935.11,3052.32 2948.43,3052.32 2961.74,3052.32 2975.06,3052.32 2988.38,3052.32 3001.7,3052.32 2648.42,3053.65 2670.36,3053.68 2166.82,3055.25 2246.41,3054.85 2411.47,3057.62 2473.17,3057.49 2047.11,3058.33 2133.97,3059.13 2397.55,3059.11 2087.59,3060.14 2215.49,3060.24 2294.92,3059.99 2382.56,3059.87 2682.49,3060.2 2659.87,3061.3 2255.12,3061.51 2325.61,3061.74 3475.51,3061.37 3488.84,3061.37 2022.58,3063.01 2458.38,3062.55 2102.63,3063.58 2115.78,3063.89 2369.36,3064.05 2620.85,3064.79 2205.74,3065.55 2285.53,3065.91 2694.84,3066.29 2174.04,3067.26 2337.05,3066.4 2482.91,3067.23 2037.37,3068.07 2420.55,3067.97 2672,3067.82 2163.14,3068.69 2246.41,3068.62 2391.93,3069.83 2078.52,3070.49 2126.71,3070.83 2707.75,3071.07 2468.11,3072.28 1988.3,3073.17 2012.84,3072.74 2297.09,3073.2 2215.49,3074.01 2684.35,3073.91 2093.34,3074.87 2255.14,3075.25 2329.6,3075.03 2378.47,3074.39 3475.51,3075.06 3488.84,3075.06 2105.23,3076.09 2720.79,3075.49 2492.65,3076.96 2027.64,3077.8 2203.08,3077.44 2403.18,3077.95 2430.04,3077.95 2285.49,3078.45 2342.51,3079.05 2734.25,3078.44 3529.15,3078.66 3569.78,3078.66 3610.4,3078.66 3651.03,3078.66 3691.65,3078.66 3732.28,3078.66 3772.9,3078.66 3813.53,3078.66 3854.15,3078.66 3894.78,3078.66 3935.4,3078.66 3976.03,3078.66 4016.65,3078.66 4057.28,3078.66 2116.54,3080.11 2157.79,3080.06 2168.95,3080.05 2696.7,3080 2068.86,3080.31 2747.75,3081.12 2477.85,3082.02 2518.22,3082.15 2558.22,3082.15 2761.48,3082.18 2003.1,3082.48 2246.25,3082.39 2775.96,3083.01 2791.83,3083.01 2805.71,3083.01 2819.59,3083.01 2833.47,3083.01 2847.36,3083.01 2861.22,3083.01 2875.1,3083.01 2888.98,3083.01 2902.87,3083.01 2916.75,3083.01 2930.61,3083.01 2944.49,3083.01 2958.38,3083.01 2972.26,3083.01 2986.14,3083.01 3000,3083.01 3013.89,3083.01 3027.77,3083.01 3041.65,3083.01 3055.53,3083.01 3069.4,3083.01 3083.28,3083.01 3097.16,3083.01 3111.04,3083.01 3124.92,3083.01 3138.79,3083.01 3152.67,3083.01 3166.55,3083.01 3180.43,3083.01 3194.31,3083.01 3208.18,3083.01 3222.06,3083.01 3235.94,3083.01 3249.82,3083.01 3263.71,3083.01 3277.57,3083.01 3291.44,3083.01 3305.3,3083.01 3319.16,3083.01 2388.63,3083.67 2083.66,3085.29 2709.61,3084.77 2301.29,3086.18 2413.35,3087.24 2502.38,3086.7 2017.9,3087.54 2214.84,3087.77 2439.78,3087.68 2255.63,3089.11 2722.65,3089.2 3475.51,3088.75 3488.84,3088.75 2059.13,3090.05 2106.37,3089.4 2150.53,3090.27 2198.34,3090.22 2338.43,3089.89 2350.65,3090.15 1993.37,3092.22 2161.11,3091.37 2286.82,3091.73 2487.59,3091.76 2736.1,3092.14 2398.8,3092.96 2608.97,3093.47 2649.54,3093.47 2073.92,3095.11 2749.61,3094.83 2244.9,3096.09 2763.34,3095.89 2008.16,3097.28 2423.52,3096.53 2512.27,3096.59 2777.82,3096.72 2791.7,3096.72 2805.58,3096.72 2819.46,3096.72 2833.34,3096.72 2847.22,3096.72 2861.11,3096.72 2874.99,3096.72 2888.85,3096.72 2902.73,3096.72 2916.62,3096.72 2930.5,3096.72 2944.38,3096.72 2958.26,3096.72 2972.14,3096.72 2986.02,3096.72 2999.89,3096.72 3013.77,3096.72 3027.65,3096.72 3041.53,3096.72 3055.42,3096.72 3069.28,3096.72 3083.16,3096.72 3097.04,3096.72 3110.93,3096.72 3124.81,3096.72 3138.67,3096.72 3152.55,3096.72 3166.44,3096.72 3180.32,3096.72 3194.2,3096.72 3208.06,3096.72 3221.95,3096.72 3235.83,3096.72 3249.71,3096.72 3263.59,3096.72 3277.46,3096.72 3291.32,3096.72 2449.51,3097.42 3305.18,3097.85 3319.05,3097.85 2096.21,3098.69 2307.4,3098.67 2049.39,3099.79 2139.95,3100.07 2360.45,3099.82 2151.53,3101.26 2211.76,3101.19 2257.36,3100.68 1983.63,3102.08 2349.49,3101.5 2408.96,3102.25 2497.32,3101.49 2191.64,3102.36 3475.51,3102.44 3488.84,3102.44 2064.19,3104.85 2290.65,3104.96 1958.2,3105.64 2433.68,3105.82 1998.43,3107.01 2459.25,3107.16 2522.07,3106.7 2086.04,3107.98 2370.62,3109.11 2039.65,3109.53 2241.39,3109.4 2315.42,3110.09 2128.71,3110.46 2141.79,3111 2507.06,3111.23 1973.96,3112.3 2260.54,3111.61 2360.1,3112.07 2419.13,3111.54 2183.04,3113.11 3305.35,3112.68 3319.16,3112.68 2206.02,3113.71 2054.45,3114.58 2443.85,3115.11 3475.51,3116.12 3488.84,3116.12 1988.81,3116.87 2075.87,3117.27 2297.11,3117.12 2468.99,3116.9 2531.49,3116.86 2250.19,3117.39 2029.92,3119.26 2380.78,3118.4 3529.15,3119.29 3569.78,3119.29 3610.4,3119.29 3651.03,3119.29 3691.65,3119.29 3732.28,3119.29 3772.9,3119.29 3813.53,3119.29 3854.15,3119.29 3894.78,3119.29 3935.4,3119.29 3976.03,3119.29 4016.65,3119.29 4057.28,3119.29 2118.48,3120.23 2325.06,3120.05 2132.06,3120.74 2429.3,3120.83 2516.49,3121.27 2236.33,3122.21 2369.79,3121.85 2558.22,3122.15 2597.09,3122.15 2637.66,3122.15 2678.22,3122.15 2718.78,3122.15 2759.34,3122.15 2799.9,3122.15 2840.46,3122.15 2881.02,3122.15 2921.58,3122.15 2962.14,3122.15 3002.7,3122.15 3043.26,3122.15 3083.82,3122.15 3124.38,3122.15 3164.94,3122.15 3205.5,3122.15 3246.06,3122.15 3286.63,3122.15 1964.5,3122.61 2173.49,3123.04 2265.02,3122.54 2044.71,3124.32 2197.86,3124.79 2454.01,3124.39 1979.51,3127.02 2065.71,3126.55 2478.72,3126.63 2306.03,3127.61 2390.95,3127.68 2541.17,3127.46 3305.35,3127.52 3319.16,3127.52 2020.18,3129 2108.31,3129.52 2247.77,3129.59 2334.8,3129.79 2439.46,3130.11 3475.51,3129.81 3488.84,3129.81 2122.32,3130.47 2379.27,3131.24 2525.79,3131.42 1955.23,3133.21 2163.76,3132.77 2270.76,3133.09 2034.98,3134.06 2229.65,3134.25 2464.18,3133.68 2188.22,3134.63 2055.54,3135.84 2488.55,3136.27 1970.2,3137.17 2401.12,3136.97 2258.26,3137.47 2315.77,3137.34 1925.77,3139.02 2010.45,3138.74 2098.15,3138.81 2550.43,3138.45 2112.58,3140.21 2344.53,3139.52 2449.63,3139.4 2240.99,3141.16 2388.75,3140.62 2535.1,3141.57 2154.02,3142.51 2474.35,3142.97 3305.35,3142.36 3318.46,3142.36 2025.24,3143.79 2279.32,3143.88 3331.57,3143.43 3344.67,3143.43 3357.78,3143.43 3370.89,3143.43 3383.99,3143.43 3397.1,3143.43 3410.2,3143.43 3423.31,3143.43 3436.42,3143.43 3449.52,3143.43 3462.63,3143.43 3475.74,3143.43 3488.84,3143.43 1946.22,3144.43 2045.38,3145.13 2178.48,3144.36 2221.04,3145 2411.28,3146.26 2325.51,3147.08 2497.86,3146.43 1961.37,3147.74 2087.98,3148.09 2265.89,3147.51 2001.15,3148.9 2354.27,3149.26 2459.79,3148.69 2102.85,3149.95 2398.23,3150.01 2558.87,3149.4 2144.28,3152.25 2232.81,3152.2 2484.51,3152.26 2543.52,3152.46 2015.5,3153.53 2168.74,3154.1 2288.67,3153.99 2035.21,3154.42 2211.58,3155 1937.66,3155.58 2421.45,3155.55 2335.24,3156.82 2507.16,3156.58 3305.35,3157.19 3318.46,3157.19 3331.57,3157.19 3344.67,3157.19 3357.78,3157.19 3370.89,3157.19 3383.99,3157.19 3397.1,3157.19 3410.2,3157.19 3423.31,3157.19 3436.42,3157.19 3449.52,3157.19 3462.63,3157.19 3475.74,3157.19 3488.84,3157.19 2077.81,3157.38 2469.96,3157.98 1952.99,3158.66 1991.85,3159.05 2274.15,3158.58 2364.01,3159 2093.11,3159.68 2407.72,3159.39 3529.15,3159.91 3569.78,3159.91 3610.4,3159.91 3651.03,3159.91 3691.65,3159.91 3732.28,3159.91 3772.9,3159.91 3813.53,3159.91 3854.15,3159.91 3894.78,3159.91 3935.4,3159.91 3976.03,3159.91 4016.65,3159.91 4057.28,3159.91 2567.58,3160.84 2134.55,3161.98 2494.06,3162.11 2598.22,3162.15 2637.66,3162.15 2678.22,3162.15 2881.02,3162.15 2962.14,3162.15 3002.7,3162.15 3043.26,3162.15 3083.82,3162.15 3124.38,3162.15 3164.94,3162.15 3205.5,3162.15 3246.06,3162.15 3286.63,3162.15 2005.76,3163.27 2223.24,3162.4 2718.78,3162.41 2759.34,3162.41 2799.9,3162.41 2840.46,3162.41 2921.58,3162.41 2025.04,3163.71 2159.01,3163.84 2298.41,3163.72 2551.91,3163.39 2201.84,3164.74 2431.61,3164.84 1929.35,3167.02 2067.65,3166.67 2344.98,3166.55 2480.12,3167.27 2516.03,3167.12 2283.43,3168.59 2373.75,3168.73 2417.2,3168.78 1944.61,3169.59 1983.21,3169.77 2083.37,3169.42 1902.34,3171.06 2124.81,3171.72 2213.51,3172.13 1996.03,3173.01 2014.88,3172.99 2503.57,3172.45 2575.79,3172.61 2149.27,3173.57 2308.15,3173.46 2441.78,3174.12 2192.11,3174.48 2560.25,3174.34 2057.48,3175.96 2354.72,3176.29 2490.29,3176.55 2426.68,3178.17 2524.41,3178.04 1921.41,3179.01 2073.64,3179.16 2229.63,3178.54 2269.63,3178.54 2293.35,3178.52 2383.48,3178.47 1936.82,3180.94 1974.82,3180.7 2004.71,3182.28 2115.07,3181.46 2203.77,3181.87 1987.31,3183.13 2317.88,3183.2 2512.72,3182.84 2139.53,3183.31 2182.37,3184.21 2451.95,3183.41 2583.23,3184.29 2047.32,3185.25 2364.45,3186.03 2500.23,3186.09 2567.64,3185.96 2303.09,3188.25 2393.22,3188.21 2436.16,3187.55 2063.9,3188.89 2532.79,3188.96 1913.88,3190.82 2105.34,3191.19 1966.45,3191.63 1994.55,3191.57 2194.03,3191.61 1929.42,3192.56 1978.45,3192.86 2129.8,3193.05 2327.62,3192.93 2462.11,3192.7 2522,3192.91 2172.63,3193.95 2037.15,3194.53 2374.19,3195.76 2445.96,3196.13 2509.96,3195.82 2590.87,3196.47 2312.83,3197.99 2402.96,3197.94 2575.04,3197.57 2054.16,3198.63 2095.6,3200.93 2540.42,3200.43 3529.15,3200.54 3569.78,3200.54 3610.4,3200.54 3651.03,3200.54 3691.65,3200.54 3732.28,3200.54 3772.9,3200.54 3813.53,3200.54 3854.15,3200.54 3894.78,3200.54 3935.4,3200.54 3976.03,3200.54 4016.65,3200.54 4057.28,3200.54 1985.47,3202.16 2184.29,3201.34 2472.28,3201.99 2637.66,3202.15 2678.22,3202.15 2881.02,3202.15 2962.14,3202.15 3002.7,3202.15 3043.26,3202.15 3083.82,3202.15 3124.38,3202.15 3164.94,3202.15 3205.5,3202.15 3246.06,3202.15 3286.63,3202.15 3327.19,3202.15 3367.75,3202.15 3408.31,3202.15 3448.87,3202.15 3489.43,3202.15 1906.62,3203.02 1959.06,3203.24 2120.06,3202.78 2337.36,3202.67 2718.78,3202.66 2759.34,3202.66 2799.9,3202.66 2840.46,3202.66 2921.58,3202.66 1922.02,3204.17 2027.01,3203.85 2162.9,3203.69 2530.58,3204.91 2383.93,3205.5 2455.44,3205.52 2519.7,3205.56 2322.56,3207.73 2412.69,3207.68 1873.55,3208.74 2044.6,3208.54 2582.31,3209.27 2597.94,3208.89 2085.86,3210.67 2174.56,3211.08 1975.78,3211.93 2482.07,3211.67 2548.23,3211.81 2110.32,3212.52 2347.1,3212.41 2017.28,3213.59 2153.16,3213.42 1951.66,3214.86 2393.66,3215.24 1899.8,3215.68 1915.35,3216.22 2420.91,3215.78 2463.78,3216.22 2528.64,3216.04 2332.3,3217.47 2539.26,3217.52 2035.66,3219.01 2189.63,3218.79 2229.63,3218.79 2269.63,3218.79 2309.63,3218.79 2076.12,3220.41 2164.82,3220.82 2604.36,3221.23 2356.83,3222.14 2491.81,3221.41 2588.66,3221.48 1967.6,3223.17 2101.34,3222.96 2143.42,3223.16 2007.54,3223.33 2429.24,3224.15 2555.16,3223.69 2402.36,3225.92 1944.56,3226.66 2342.04,3227.2 1893.36,3228.05 2471.21,3227.6 2535.89,3227.74 1908.99,3228.43 2066.42,3230.17 2083.09,3229.65 2015.2,3231.3 2028.22,3230.6 2155.08,3230.56 2501.4,3231.29 2366.57,3231.88 2547.71,3232.15 2133.68,3232.9 1998.15,3233.4 2438.13,3233.64 2595.02,3233.7 2610.86,3234.06 2093.6,3234.34 1961.78,3235.57 2353.1,3235.72 2561.52,3235.9 2409.47,3237.71 1938.2,3238.87 1950.36,3238.43 2425.5,3238.84 2145.35,3240.29 2477.96,3239.6 1887.22,3240.91 1902.63,3240.64 2057.68,3240.82 2075.24,3240.83 2541.13,3240.48 3529.15,3241.16 3569.78,3241.16 3610.4,3241.16 3651.03,3241.16 3691.65,3241.16 3732.28,3241.16 3772.9,3241.16 3813.53,3241.16 3854.15,3241.16 3894.78,3241.16 3935.4,3241.16 3976.03,3241.16 4016.65,3241.16 4057.28,3241.16 2375.85,3242.06 2637.66,3242.15 2678.22,3242.15 2881.02,3242.15 2962.14,3242.15 3002.7,3242.15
